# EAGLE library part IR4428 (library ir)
DUAL LOW SIDE DRIVER Source: ID4426.pdf
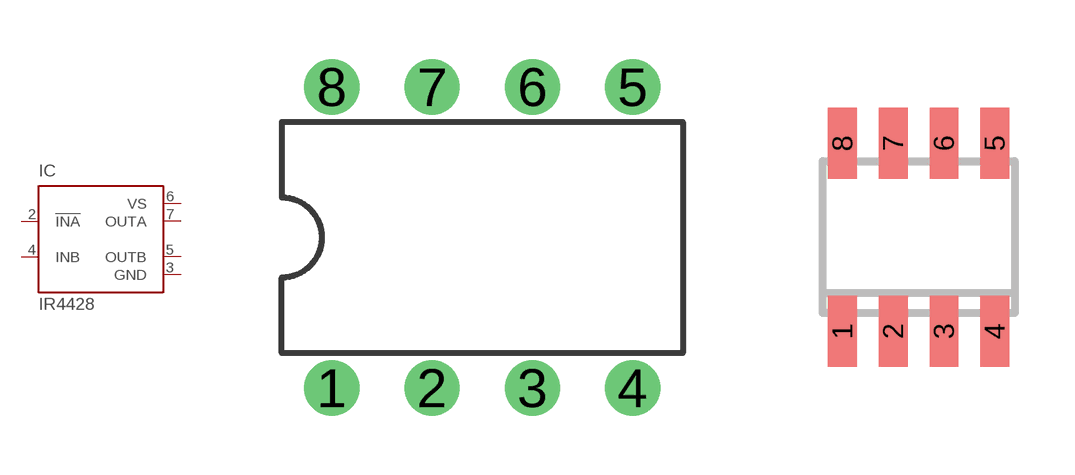
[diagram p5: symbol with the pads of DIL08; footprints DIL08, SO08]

Designator prefix IC

## IR4428 (MF: INTERNATIONAL RECTIFIER(IR); MPN: IR4428PBF; OC_FARNELL: 1023268; OC_NEWARK: 19K8464)  [DIL08]
2  !INA  in
3  GND  pwr
4  INB  in
5  OUTB  out
6  VS  pwr
7  OUTA  out

## IR4428S (MF: INTERNATIONAL RECTIFIER(IR); MPN: IR4428STR; OC_FARNELL: 1023269; OC_NEWARK: 30C0206)  [SO08]
Pads as for DIL08

## Footprint DIL08 (pad centres in mm)
Dual In Line Package
drill 0.8 pad 1.4 round: 1 -3.81,-3.81; 2 -1.27,-3.81; 3 1.27,-3.81; 4 3.81,-3.81; 5 3.81,3.81; 6 1.27,3.81; 7 -1.27,3.81; 8 -3.81,3.81

## Footprint SO08 (pad centres in mm)
8 Lead SOIC Data Sheet No. PD60212 Rev A Source: www.irf.com .. ir2520.pdf
smd 0.72 x 1.78: 1 -1.905,-2.35; 2 -0.635,-2.35; 3 0.635,-2.35; 4 1.905,-2.35; 5 1.905,2.35; 6 0.635,2.35; 7 -0.635,2.35; 8 -1.905,2.35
